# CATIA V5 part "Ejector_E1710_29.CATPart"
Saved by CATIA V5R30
Part number: Vyhazovac_7x160_6
Nomenclature: E1710/7x160
Description: MEUSBURGER
Property "Material": "1.221"
Publications: "__DrillHole", "Base"
Bounding box of the stored display mesh (mm): x -5.992 to 5.992, y -5.992 to 5.992, z 0 to 151
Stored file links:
  E:\Bakalarka\Model\Forma_v7\Ejector_E1710_29.CATPart
  E:\dev\MoldDesign\intel_a\startup\components\MoldCatalog\Ejector\Meusburger\Ejector_E1710\TableE1710.txt
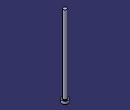
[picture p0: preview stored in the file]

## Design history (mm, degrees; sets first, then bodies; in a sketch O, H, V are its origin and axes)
Parameters
  Ref = "E1710/7x160" {design table}
  D1 = 7 mm {design table}
  D3 = 12 mm {design table}
  L = 160 mm {design table}
  L3 = 5 mm {design table}
  R = 0.5 mm {design table}
  k_d3 = 13 mm {design table}
  k_d1 = 7.2 mm {design table}
  k_F = 0.5 mm {design table}
  kl = 17 mm {design table}
  Mat = "1.221" {design table}
  HeatTreat = "ISO6751" {design table}
  Offset_Parting = 10 mm
  Anti_Rotation = "Normal"
  Anti_Rotation_D = 4 mm
  Anti_Rotation_D_Icut = 4 mm
  Add_Length_L = 1.3377 mm
  Add_Length_D3 = 0 mm
  SupplierRef = "Meusburger 2017"
  BmpRef = "F_MldEjectorD1"
  DrillHole_Length = 225 mm
  ValidationTest = false
  Anti_Rotation_D_min = 4 mm {= OffSet_D1 /2}
  Anti_Rotation_D_max = 5.925 mm {= D3/2-0.075mm}
  Anti_Rotation_D_ref = 4 mm {= Anti_Rotation_D}
  Anti_Rotation_D_Icut_ref = 4 mm {= Anti_Rotation_D_Icut}
  Anti_Rotation_Ref_Icut = 2.3246 mm
  Offset_L = 20 mm
  D = 7 mm {= D1}
  OffSet_D1 = 8 mm {= D1+2*R}
  OffSet_D3 = 13 mm {= D3+1mm}
  XG_Split = -125.5 mm
  YG_Split = -33 mm
  ZG_Split = -198 mm
  DirX_Split = 0 mm
  DirY_Split = 0 mm
  DirZ_Split = 1 mm
Set1 "BaseBody"
  Point1 "Base": (0, 0, 0)
  Plane1: type Offset, RefPlane xy-plane, Offset 225 {= DrillHole_Length}, reversed
  Sketch1 "Sketch.2" on xy-plane, origin (0, 0, 0), H (1, 0, 0), V (0, 1, 0)
    point P1 (-0.46, 1.1623)
    point P2 (0.46, 1.1623)
    construction line L1 (-0.46, 1.1623) -> (0.46, 1.1623)
    point P3 (0.46, -1.1623)
    line L2 (0.46, -1.1623) -> (0.46, 1.1623)
    point P4 (-0.46, -1.1623)
    construction line L3 (0.46, -1.1623) -> (-0.46, -1.1623)
    line L4 (-0.46, 1.1623) -> (-0.46, -1.1623)
    point P5 (-0.21, 1.1623)
    arc A1 centre (-0.21, 1.1623) radius 0.25 from (-0.21, 1.4123) to (-0.46, 1.1623) ccw
    point P7 (0.21, 1.1623)
    point P8 (0.21, 1.4123)
    arc A2 centre (0.21, 1.1623) radius 0.25 from (0.46, 1.1623) to (0.21, 1.4123) ccw
    line L5 (-0.21, 1.4123) -> (0.21, 1.4123)
    point P9 (-0.46, -1.1623)
    arc A3 centre (-0.21, -1.1623) radius 0.25 from (-0.46, -1.1623) to (-0.21, -1.4123) ccw
    point P11 (0.21, -1.4123)
    line L6 (-0.21, -1.4123) -> (0.21, -1.4123)
    point P12 (0.46, -1.1623)
    arc A4 centre (0.21, -1.1623) radius 0.25 from (0.21, -1.4123) to (0.46, -1.1623) ccw
    point P14 (-0.46, 1.1623)
    point P15 (-0.46, -1.1623)
    point P16 (0.46, 1.1623)
    point P17 (0.46, -1.1623)
    reference projected circle E1 centre (0, 0) radius 1.25 from edge [face of Shaft1 from Sketch2.L3 | face of Shaft1 from Sketch2.L4]
    reference projected circle E2 centre (0, 0) radius 1.25 from edge [face of Shaft1 from Sketch2.L3 | face of Shaft1 from Sketch2.L4]
    reference projected circle E3 centre (0, 0) radius 1.25 from edge [face of Shaft1 from Sketch2.L3 | face of Shaft1 from Sketch2.L4]
    reference projected circle E4 centre (0, 0) radius 1.25 from edge [face of Shaft1 from Sketch2.L3 | face of Shaft1 from Sketch2.L4]
    point P18 (-0.46, -1.1623)
    point P19 (-0.21, -1.4123)
    point P20 (0.21, -1.4123)
    point P21 (0.46, -1.1623)
    point P22 (-0.21, -1.4123)
    point P23 (0.21, -1.4123)
    distance P14 P15 = 2.3246 (reference)
    distance P16 P17 = 2.3246 (reference)
    distance L1 P14 = 0 (reference)
    radius A1 = 3.5
    distance L4 V = 4.01
    distance L2 V = 5.935
    distance L5 L6 = 12
    horizontal: L1 H, L3 H, L5 H
    vertical: L2 V, L4 V
    coincidence: P5 L1, P7 L1, P3 P12, P14 L4, P15 L4, P16 L2, P17 L2, P14 E1, P15 E2, P16 E3, P17 E4, P3 P21, P4 P18, P20 P23, P19 P22
    tangency: A1 L4, A2 L2, A2 L5, A1 L5
    symmetry: P1 P9 H, A1 A3 H, P8 P11 H, L5 L6 H, P2 P12 H, A2 A4 H
  DatumSurface1
Body1 "PartBody" (main body)
  Sketch2 "Sketch.1" on zx-plane, origin (0, 0, 0), H (-1, 0, 0), V (0, 0, 1)
    point P1 (0, 160)
    line L1 (3.5, 160) -> (0, 160)
    line L2 (3.5, 5) -> (3.5, 160)
    line L3 (6, 5) -> (3.5, 5)
    line L4 (6, 0) -> (6, 5)
    point P5 (0, 0)
    line L5 (0, 0) -> (6, 0)
    point P6 (0, 160)
    axis line L6 (0, 160) -> (0, 0)
    point P7 (0, 0)
    point P8 (3.5, 5)
    point P9 (3.5, 5)
    line L7 (0, 160) -> (0, 0)
    distance L5 L3 = 5 {= L3}
    distance L5 L1 = 160 {= L}
    distance L2 L6 = 3.5 {= D1 /2}
    distance L4 L6 = 6 {= D3 /2}
    coincidence: L6 P5, P1 L6, L5 H, L6 V, P7 O, P6 P1, P8 P9
    vertical: L2 V, L7 V
    horizontal: L1 H
  Shaft1 "Shaft.1": profile Sketch2, axis Sketch2.L6, angle 360
  Pocket1 "Pocket.1": profile Sketch1, direction (0, 0, 1), length 6, outer side, deactivated
  Pocket2 "Pocket.2": profile Sketch1, direction (0, 0, 1), length 6, outer side, deactivated
  Fillet1: radius 0.5 {= R}, on edge [face of Shaft1 from Sketch2.L2 | face of Shaft1 from Sketch2.L3]
  Pocket3: profile face of Shaft1 from Sketch2.L1, direction along face of Shaft1 from Sketch2.L1 reversed, up to face of DatumSurface1
Body2 "__DrillHole"
  Sketch3 "Sketch.3" on face of Shaft1, origin (0, 0, 0), H (1, 0, 0), V (0, -1, 0)
    point P1 (0, 0)
    reference projected point E1 (0, 0) from Point1
    coincidence: E1 P1
  Hole1 "Hole.1": placed by Sketch3, at (0, 0, 0) direction (0, 0, 1), diameter 8 {= OffSet_D1}, depth 140 {= L-Offset_L}
  Sketch4 "Sketch.4" on face of Shaft1, origin (0, 0, 0), H (1, 0, 0), V (0, -1, 0)
    point P1 (0, 0)
    reference projected point E1 (0, 0) from Point1
    coincidence: E1 P1
  Hole2 "Hole.2": placed by Sketch4, at (0, 0, 0) direction (0, 0, 1), diameter 7 {= D1}, depth 160 {= L}
  Sketch5 "Sketch.5" on face of Shaft1 from Sketch2.L3, origin (0, 0, 5), H (1, 0, 0), V (0, 1, 0)
    point P1 (0, 0)
    reference projected point E1 (0, 0) from Point1
    coincidence: E1 P1
  Hole3 "Hole.3": placed by Sketch5, at (0, 0, 5) direction (0, 0, -1), diameter 13 {= OffSet_D3}, depth 230 {= L3 +DrillHole_Length}
  Chamfer1: length 0.5 {= k_F}, angle 45, on edge [face of Hole1 | face of Hole3]
  Body3 "__Body.1"
    Pocket4 "Pocket.3": profile Sketch1, direction (0, 0, -1), length 225, opposite side length 5, deactivated
  Assemble1: tool Body3
  Chamfer2: length 0.5 {= k_F}, angle 45, on edge [start face of Pocket4 | face of Hole1], deactivated
  Body4 "__Body.2"
    Pocket5 "Pocket.4": profile Sketch1, direction (0, 0, -1), length 225, opposite side length 5, deactivated
  Assemble2: tool Body4
  Chamfer3: length 0.5 {= k_F}, angle 45, on edge [start face of Pocket5 | face of Hole1], deactivated
Relations
  design table "TableE1710", configuration 278, drives Ref, D1, D3, L, L3, R, k_d3, k_d1, k_F, kl, Mat, HeatTreat
  Offset_L = 20mm (deactivated)
  rule "Cut_Head_rule":
    let sketch_cut (length)
    let PartBody_Pocket_Sketch (Boolean)
    let I_PartBody_Pocket (Boolean)
    let D_PartBody_Pocket (Boolean)
    let N_DrillHole_Hole (Boolean)
    let N_DrillHole_Hole_Sketch (Boolean)
    let I_DrillHole_Pocket (Boolean)
    let D_DrillHole_Pocket (Boolean)
    /* --------------------------------------------------------------------------------------*/
    if Anti_Rotation =="Normal"
    {
    	sketch_cut=Anti_Rotation_D_max
    	PartBody_Pocket_Sketch = false
    	I_PartBody_Pocket = false
    	D_PartBody_Pocket = false
    	N_DrillHole_Hole = true
    	N_DrillHole_Hole_Sketch = true
    	I_DrillHole_Pocket = false
    	D_DrillHole_Pocket = false
    	Chamfer1.Activity= true
    	Chamfer2.Activity= false
    	Chamfer3.Activity= false
    }
    if Anti_Rotation == "I_Cut"
    {
    	sketch_cut=Anti_Rotation_D_Icut_ref
    	PartBody_Pocket_Sketch = true
    	I_PartBody_Pocket = true
    	D_PartBody_Pocket = false
    	N_DrillHole_Hole = false
    	N_DrillHole_Hole_Sketch = false
    	I_DrillHole_Pocket = true
    	D_DrillHole_Pocket = false
    	Chamfer1.Activity= false
    	Chamfer2.Activity= true
    	Chamfer3.Activity= false
    }
    if Anti_Rotation =="D_Cut"
    {
    	sketch_cut=Anti_Rotation_D_max
    	PartBody_Pocket_Sketch = true
    	I_PartBody_Pocket = false
    	D_PartBody_Pocket = true
    	N_DrillHole_Hole = false
    	N_DrillHole_Hole_Sketch = false
    	I_DrillHole_Pocket = false
    	D_DrillHole_Pocket = true
    	Chamfer1.Activity= false
    	Chamfer2.Activity= false
    	Chamfer3.Activity= true
    }
    /* --------------------------------------------------------------------------------------*/
    Sketch1.distance(L2 V) = sketch_cut+0.01mm
    Sketch1.distance(L4 V) =Anti_Rotation_D_ref+0.01mm
    Sketch1.radius(A1) =D/2
    Pocket4.FirstLimit.Depth = DrillHole_Length
    Pocket5.FirstLimit.Depth = DrillHole_Length
    Pocket1.FirstLimit.Depth = L3+1mm
    Pocket2.FirstLimit.Depth = L3+1mm
    Pocket4.SecondLimit.Depth = L3
    Pocket5.SecondLimit.Depth =L3
    Pocket1.Activity = I_PartBody_Pocket
    Pocket2.Activity = D_PartBody_Pocket
    Sketch1.Activity =PartBody_Pocket_Sketch
    Hole3.Activity= N_DrillHole_Hole
    Sketch5.Activity = N_DrillHole_Hole_Sketch
    Pocket4.Activity = I_DrillHole_Pocket
    Pocket5.Activity  = D_DrillHole_Pocket
  rule "Anti_Rotation_Icut_constrain":
    let Ref1(length)
    let Ref2(length)
    let Ref3(length)
    let Diam1(length)
    let Diam2(length)
    let Add_Length_Lmin (length)
    Ref1=Sketch1.distance(P14 P15)
    Ref2=Sketch1.distance(P16 P17)
    Diam1=D
    Diam2=D3
    /* --------------------------------------------------------------------*/
    if Ref1 >Ref2
    	Anti_Rotation_Ref_Icut = Ref1
    else
    	Anti_Rotation_Ref_Icut  =Ref2
    Add_Length_D3 .InferiorRange=Anti_Rotation_Ref_Icut /2+Diam1/2 -Diam2/2
    if Add_Length_D3 .InferiorRange<0mm
    	Add_Length_D3 .InferiorRange=0mm
    if ValidationTest == "true"
    	Ref3   = 2*Add_Length_L +Anti_Rotation_Ref_Icut  +2*Diam1/2
    else
    	Ref3  =Diam2+2*Add_Length_D3
    if Ref3 <Diam2
    {
    	Ref3 =Diam2
    }
    /* --------------------------------------------------------------------*/
    Sketch1.distance(L5 L6) = Ref3
    Add_Length_L .InferiorRange=Diam2/2-Anti_Rotation_Ref_Icut/2-Diam1/2
    Add_Length_Lmin=Diam2/2-Anti_Rotation_Ref_Icut/2-Diam1/2
    if Add_Length_Lmin<0mm
    	Add_Length_L .InferiorRange=0mm
    else
    	Add_Length_L .InferiorRange=Add_Length_Lmin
